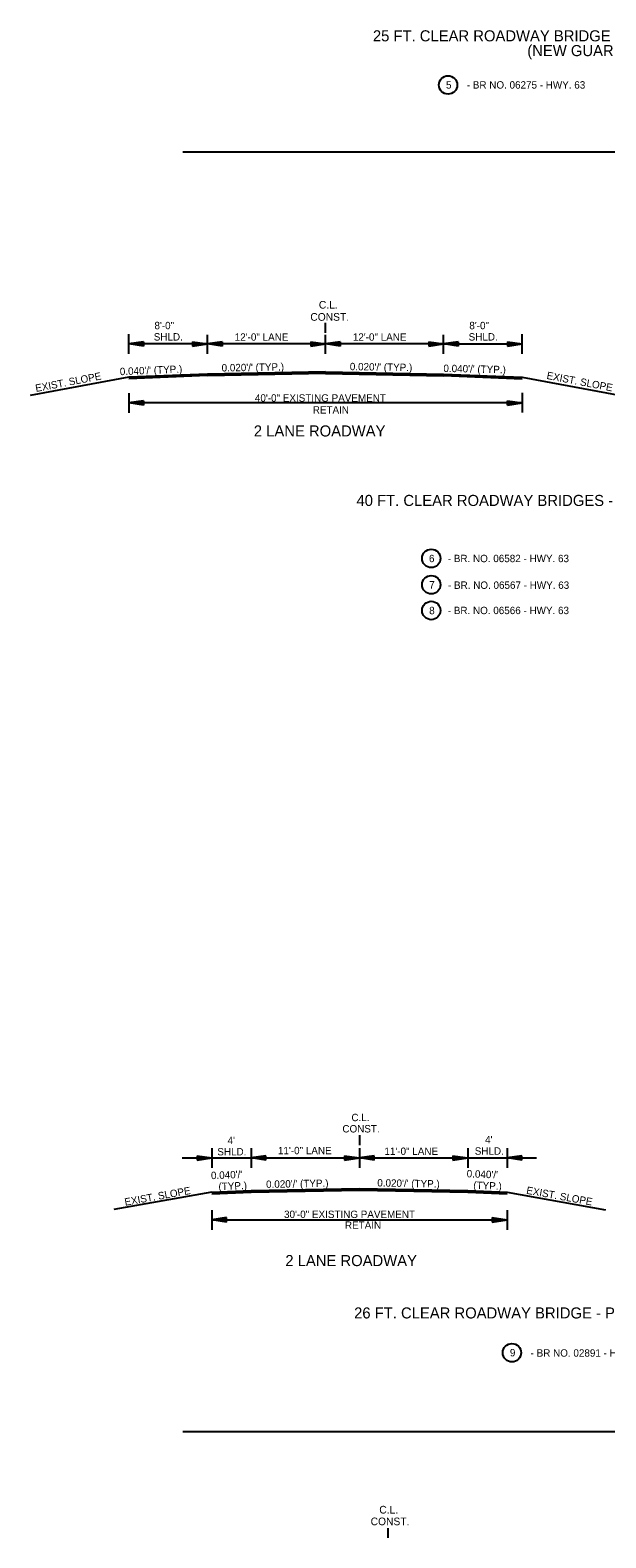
# Model space of a CAD drawing. Extents: x 545241 to 1930787, y -1971772 to 596640.
# Drawn here: x 546732 to 547317, y -1951831 to -1950299 of the extents above; entities that cross this region are included whole.
import ezdxf

# ---------------------------------------------------------------- set-up
doc = ezdxf.new("R2010")
doc.units = 0
doc.layers.add('R_Border', color=7, linetype='Continuous')
doc.layers.add('R_Draft', color=7, linetype='Continuous')

# ---------------------------------------------------------------- blocks, each defined once
blk = doc.blocks.new('ARROW')
at = {"layer": 'R_Draft'}
for p, q in [((-2, 0.3), (0, 0)), ((-2, 0.3), (-2, -0.3)), ((-2, 0.25), (-0.334, 0)), ((-2, 0.199), (-0.678, 0)), ((-2, 0.149), (-1.011, 0)), ((-2, 0.097), (-1.35, 0)), ((-2, 0.047), (-1.684, 0)), ((-2, -0.3), (0, 0)), ((-2, -0.098), (-1.35, 0)), ((-2, -0.199), (-0.678, 0)), ((-2, -0.25), (-0.334, 0)), ((-2, -0.149), (-1.011, 0)), ((-2, -0.047), (-1.684, 0))]:
    blk.add_line(p, q, dxfattribs=at)
blk = doc.blocks.new('BPPOLY')
at = {"layer": 'R_Border'}
blk.add_circle((0, 0), 9.34, dxfattribs=at)

msp = doc.modelspace()

# ---------------------------------------------------------------- linework, layer by layer
at = {"layer": 'R_Border'}
for p, q in [((546887.2, -1950422.9), (547733.9, -1950422.9)), ((547066.6, -1951422.1), (547066.6, -1951432.1)), ((546886.6, -1951445.1), (547246.6, -1951445.1)), ((546916.6, -1951435.1), (546916.6, -1951455.1)), ((546956.6, -1951435.1), (546956.6, -1951455.1)), ((547066.6, -1951435.1), (547066.6, -1951455.1)), ((547176.6, -1951435.1), (547176.6, -1951455.1)), ((547216.6, -1951435.1), (547216.6, -1951455.1)), ((546916.6, -1951479.8), (546817.1, -1951497.3)), ((547216.6, -1951479.8), (547316.6, -1951497.8)), ((546916.6, -1951498), (546916.6, -1951518)), ((546916.6, -1951508), (547216.6, -1951508)), ((547216.6, -1951498), (547216.6, -1951518)), ((546887.2, -1951722.9), (547733.9, -1951722.9))]:
    msp.add_line(p, q, dxfattribs=at)
for points in [[(546916.6, -1951479.8), (546956.6, -1951478.2), (547066.6, -1951476), (547176.6, -1951478.2), (547216.6, -1951479.8)], [(546916.6, -1951480.1), (546956.6, -1951478.5), (547066.6, -1951476.3), (547176.6, -1951478.5), (547216.6, -1951480.1)], [(546916.6, -1951480.4), (546956.6, -1951478.8), (547066.6, -1951476.6), (547176.6, -1951478.8), (547216.6, -1951480.4)], [(546916.6, -1951480.7), (546956.6, -1951479.1), (547066.6, -1951476.9), (547176.6, -1951479.1), (547216.6, -1951480.7)], [(546916.6, -1951481), (546956.6, -1951479.4), (547066.6, -1951477.2), (547176.6, -1951479.4), (547216.6, -1951481)], [(546916.6, -1951481.3), (546956.6, -1951479.7), (547066.6, -1951477.5), (547176.6, -1951479.7), (547216.6, -1951481.3)], [(546916.6, -1951481.6), (546956.6, -1951480), (547066.6, -1951477.8), (547176.6, -1951480), (547216.6, -1951481.6)]]:
    msp.add_lwpolyline(points, dxfattribs=at)
for centre in [(547156.7, -1950354.8), (547139.6, -1950835.9), (547139.6, -1950862.7), (547139.6, -1950888.8)]:
    msp.add_circle(centre, 9.34, dxfattribs=at)
at = {"layer": 'R_Draft'}
for p, q in [((547032.1, -1950606.6), (547032.1, -1950596.6)), ((546832.1, -1950627.9), (546832.1, -1950607.9)), ((546847.1, -1950615.7), (546832.1, -1950617.9)), ((546912.1, -1950617.9), (546832.1, -1950617.9)), ((546847.1, -1950620.2), (546832.1, -1950617.9)), ((546847.1, -1950616), (546834.6, -1950617.9)), ((546847.1, -1950619.8), (546834.6, -1950617.9)), ((546847.1, -1950616.4), (546837.1, -1950617.9)), ((546847.1, -1950619.4), (546837.1, -1950617.9)), ((546847.1, -1950616.8), (546839.6, -1950617.9)), ((546847.1, -1950619), (546839.6, -1950617.9)), ((546847.1, -1950617.2), (546842.2, -1950617.9)), ((546847.1, -1950618.6), (546842.2, -1950617.9)), ((546847.1, -1950617.6), (546844.7, -1950617.9)), ((546847.1, -1950618.3), (546844.7, -1950617.9)), ((546847.1, -1950615.7), (546847.1, -1950620.2)), ((546897.1, -1950615.7), (546912.1, -1950617.9)), ((546897.1, -1950615.7), (546897.1, -1950620.2)), ((546897.1, -1950616), (546909.5, -1950617.9)), ((546897.1, -1950616.4), (546907, -1950617.9)), ((546897.1, -1950616.8), (546904.5, -1950617.9)), ((546897.1, -1950617.2), (546901.9, -1950617.9)), ((546897.1, -1950617.6), (546899.4, -1950617.9)), ((546897.1, -1950620.2), (546912.1, -1950617.9)), ((546897.1, -1950618.6), (546901.9, -1950617.9)), ((546897.1, -1950619.4), (546907, -1950617.9)), ((546897.1, -1950619.8), (546909.5, -1950617.9)), ((546897.1, -1950619), (546904.5, -1950617.9)), ((546897.1, -1950618.3), (546899.4, -1950617.9)), ((546912.1, -1950627.9), (546912.1, -1950608.7)), ((546927.1, -1950615.7), (546912.1, -1950617.9)), ((547032.1, -1950617.9), (546912.1, -1950617.9)), ((546927.1, -1950620.2), (546912.1, -1950617.9)), ((546927.1, -1950616), (546914.6, -1950617.9)), ((546927.1, -1950619.8), (546914.6, -1950617.9)), ((546927.1, -1950616.4), (546917.1, -1950617.9)), ((546927.1, -1950619.4), (546917.1, -1950617.9)), ((546927.1, -1950616.8), (546919.6, -1950617.9)), ((546927.1, -1950619), (546919.6, -1950617.9)), ((546927.1, -1950617.2), (546922.2, -1950617.9)), ((546927.1, -1950618.6), (546922.2, -1950617.9)), ((546927.1, -1950617.6), (546924.7, -1950617.9)), ((546927.1, -1950618.3), (546924.7, -1950617.9)), ((546927.1, -1950615.7), (546927.1, -1950620.2)), ((547017.1, -1950615.7), (547032.1, -1950617.9)), ((547017.1, -1950615.7), (547017.1, -1950620.2)), ((547017.1, -1950616), (547029.5, -1950617.9)), ((547017.1, -1950616.4), (547027, -1950617.9)), ((547017.1, -1950616.8), (547024.5, -1950617.9)), ((547017.1, -1950617.2), (547021.9, -1950617.9)), ((547017.1, -1950617.6), (547019.4, -1950617.9)), ((547017.1, -1950620.2), (547032.1, -1950617.9)), ((547017.1, -1950618.6), (547021.9, -1950617.9)), ((547017.1, -1950619.4), (547027, -1950617.9)), ((547017.1, -1950619.8), (547029.5, -1950617.9)), ((547017.1, -1950619), (547024.5, -1950617.9)), ((547017.1, -1950618.3), (547019.4, -1950617.9)), ((547032.1, -1950627.9), (547032.1, -1950608.7)), ((547047.1, -1950615.7), (547032.1, -1950617.9)), ((547152.1, -1950617.9), (547032.1, -1950617.9)), ((547047.1, -1950620.2), (547032.1, -1950617.9)), ((547047.1, -1950616), (547034.6, -1950617.9)), ((547047.1, -1950619.8), (547034.6, -1950617.9)), ((547047.1, -1950616.4), (547037.1, -1950617.9)), ((547047.1, -1950619.4), (547037.1, -1950617.9)), ((547047.1, -1950616.8), (547039.6, -1950617.9)), ((547047.1, -1950619), (547039.6, -1950617.9)), ((547047.1, -1950617.2), (547042.2, -1950617.9)), ((547047.1, -1950618.6), (547042.2, -1950617.9)), ((547047.1, -1950617.6), (547044.7, -1950617.9)), ((547047.1, -1950618.3), (547044.7, -1950617.9)), ((547047.1, -1950615.7), (547047.1, -1950620.2)), ((547137.1, -1950615.7), (547152.1, -1950617.9)), ((547137.1, -1950615.7), (547137.1, -1950620.2)), ((547137.1, -1950616), (547149.5, -1950617.9)), ((547137.1, -1950616.4), (547147, -1950617.9)), ((547137.1, -1950616.8), (547144.5, -1950617.9)), ((547137.1, -1950617.2), (547141.9, -1950617.9)), ((547137.1, -1950617.6), (547139.4, -1950617.9)), ((547137.1, -1950620.2), (547152.1, -1950617.9)), ((547137.1, -1950618.6), (547141.9, -1950617.9)), ((547137.1, -1950619.4), (547147, -1950617.9)), ((547137.1, -1950619.8), (547149.5, -1950617.9)), ((547137.1, -1950619), (547144.5, -1950617.9)), ((547137.1, -1950618.3), (547139.4, -1950617.9)), ((547152.1, -1950627.9), (547152.1, -1950608.7)), ((547167.1, -1950615.7), (547152.1, -1950617.9)), ((547152.1, -1950617.9), (547232.1, -1950617.9)), ((547167.1, -1950620.2), (547152.1, -1950617.9)), ((547167.1, -1950616), (547154.6, -1950617.9)), ((547167.1, -1950619.8), (547154.6, -1950617.9)), ((547167.1, -1950616.4), (547157.1, -1950617.9)), ((547167.1, -1950619.4), (547157.1, -1950617.9)), ((547167.1, -1950616.8), (547159.6, -1950617.9)), ((547167.1, -1950619), (547159.6, -1950617.9)), ((547167.1, -1950617.2), (547162.2, -1950617.9)), ((547167.1, -1950618.6), (547162.2, -1950617.9)), ((547167.1, -1950617.6), (547164.7, -1950617.9)), ((547167.1, -1950618.3), (547164.7, -1950617.9)), ((547167.1, -1950615.7), (547167.1, -1950620.2)), ((547217.1, -1950615.7), (547232.1, -1950617.9)), ((547217.1, -1950615.7), (547217.1, -1950620.2)), ((547217.1, -1950616), (547229.5, -1950617.9)), ((547217.1, -1950616.4), (547227, -1950617.9)), ((547217.1, -1950616.8), (547224.5, -1950617.9)), ((547217.1, -1950617.2), (547221.9, -1950617.9)), ((547217.1, -1950617.6), (547219.4, -1950617.9)), ((547217.1, -1950620.2), (547232.1, -1950617.9)), ((547217.1, -1950618.6), (547221.9, -1950617.9)), ((547217.1, -1950619.4), (547227, -1950617.9)), ((547217.1, -1950619.8), (547229.5, -1950617.9)), ((547217.1, -1950619), (547224.5, -1950617.9)), ((547217.1, -1950618.3), (547219.4, -1950617.9)), ((547232.1, -1950627.9), (547232.1, -1950607.9)), ((546832.1, -1950651.8), (546732, -1950670.2)), ((546912.1, -1950648.6), (546832.1, -1950651.8)), ((546912.1, -1950648.9), (546832.1, -1950652.1)), ((546912.1, -1950649.2), (546832.1, -1950652.4)), ((546912.1, -1950649.5), (546832.1, -1950652.7)), ((546912.1, -1950649.8), (546832.1, -1950653)), ((546912.1, -1950650.1), (546832.1, -1950653.3)), ((547032.1, -1950646.2), (546912.1, -1950648.6)), ((547032.1, -1950646.5), (546912.1, -1950648.9)), ((547032.1, -1950646.8), (546912.1, -1950649.2)), ((547032.1, -1950647.1), (546912.1, -1950649.5)), ((547032.1, -1950647.4), (546912.1, -1950649.8)), ((547032.1, -1950647.7), (546912.1, -1950650.1)), ((547032.1, -1950647.9), (546912.1, -1950650.3)), ((547032.1, -1950646.2), (547152.1, -1950648.6)), ((547032.1, -1950646.5), (547152.1, -1950648.9)), ((547032.1, -1950646.8), (547152.1, -1950649.2)), ((547032.1, -1950647.1), (547152.1, -1950649.5)), ((547032.1, -1950647.4), (547152.1, -1950649.8)), ((547032.1, -1950647.7), (547152.1, -1950650.1)), ((547032.1, -1950647.9), (547152.1, -1950650.3)), ((547152.1, -1950648.6), (547232.1, -1950651.8)), ((547152.1, -1950648.9), (547232.1, -1950652.1)), ((547152.1, -1950649.2), (547232.1, -1950652.4)), ((547152.1, -1950649.5), (547232.1, -1950652.7)), ((547152.1, -1950649.8), (547232.1, -1950653)), ((547152.1, -1950650.1), (547232, -1950653.3)), ((547232.1, -1950651.8), (547332.1, -1950670.2)), ((547232.1, -1950667.6), (547232.1, -1950687.6)), ((546832.1, -1950667.9), (546832.1, -1950687.9)), ((546847.1, -1950675.6), (546832.1, -1950677.9)), ((546847.1, -1950680.1), (546832.1, -1950677.9)), ((547232.1, -1950677.9), (546832.1, -1950677.9)), ((546847.1, -1950676), (546834.6, -1950677.9)), ((546847.1, -1950679.8), (546834.6, -1950677.9)), ((546847.1, -1950676.4), (546837.1, -1950677.9)), ((546847.1, -1950679.4), (546837.1, -1950677.9)), ((546847.1, -1950676.8), (546839.6, -1950677.9)), ((546847.1, -1950679), (546839.6, -1950677.9)), ((546847.1, -1950677.1), (546842.2, -1950677.9)), ((546847.1, -1950678.6), (546842.2, -1950677.9)), ((546847.1, -1950677.5), (546844.7, -1950677.9)), ((546847.1, -1950678.2), (546844.7, -1950677.9)), ((546847.1, -1950675.6), (546847.1, -1950680.1)), ((547217.1, -1950675.6), (547232.1, -1950677.9)), ((547217.1, -1950680.1), (547217.1, -1950675.6)), ((547217.1, -1950676), (547229.5, -1950677.9)), ((547217.1, -1950676.4), (547227, -1950677.9)), ((547217.1, -1950676.8), (547224.5, -1950677.9)), ((547217.1, -1950677.1), (547221.9, -1950677.9)), ((547217.1, -1950677.5), (547219.4, -1950677.9)), ((547217.1, -1950680.1), (547232.1, -1950677.9)), ((547217.1, -1950678.6), (547221.9, -1950677.9)), ((547217.1, -1950679.4), (547227, -1950677.9)), ((547217.1, -1950679.8), (547229.5, -1950677.9)), ((547217.1, -1950679), (547224.5, -1950677.9)), ((547217.1, -1950678.2), (547219.4, -1950677.9)), ((547095.6, -1951821.1), (547095.6, -1951831.1))]:
    msp.add_line(p, q, dxfattribs=at)

# ---------------------------------------------------------------- block references
at = {"layer": 'R_Border', "xscale": 7.5, "yscale": 7.5}
for p in [(546916.6, -1951445.1), (547066.6, -1951445.1), (547176.6, -1951445.1), (547216.6, -1951508)]:
    msp.add_blockref('ARROW', p, dxfattribs=at)
at = {"layer": 'R_Border', "xscale": 7.5, "yscale": 7.5, "rotation": 180}
for p in [(546956.6, -1951445.1), (547066.6, -1951445.1), (547216.6, -1951445.1), (546916.6, -1951508)]:
    msp.add_blockref('ARROW', p, dxfattribs=at)
at = {"layer": 'R_Border'}
msp.add_blockref('BPPOLY', (547221.6, -1951643), dxfattribs=at)

# ---------------------------------------------------------------- texts
for s, height, p in [('25 FT. CLEAR ROADWAY BRIDGE - POLYMER OVERLAY', 11.25, (547080.3, -1950310.5)), ('(NEW GUARDRAIL)', 11.25, (547237.2, -1950325.5)), ('5', 7.5, (547154.6, -1950358.5)), ('- BR NO. 06275 - HWY. 63', 7.5, (547175.7, -1950358.5)), ('6', 7.5, (547137.3, -1950839.7)), ('7', 7.5, (547137.5, -1950866.5)), ('8', 7.5, (547137.5, -1950892.6)), ('C.L.', 7.5, (547058.5, -1951407.7)), ('CONST.', 7.5, (547049.3, -1951419.2)), ("4' ", 7.5, (546932.6, -1951431)), ('11\'-0" LANE', 7.5, (546983.8, -1951441.3)), ("4' ", 7.5, (547194.3, -1951430.3)), ('SHLD.', 7.5, (546922.2, -1951442.5)), ('11\'-0" LANE', 7.5, (547092, -1951442)), ('SHLD.', 7.5, (547183.8, -1951441.8)), ('30\'-0" EXISTING PAVEMENT', 7.5, (546990, -1951506.1)), ('RETAIN', 7.5, (547051.9, -1951517.1)), ('2 LANE ROADWAY', 11.25, (546991.3, -1951555)), ('26 FT. CLEAR ROADWAY BRIDGE - POLYMER OVERLAY', 11.25, (547061.2, -1951608.2)), ('9', 7.5, (547219.5, -1951646.7)), ('- BR NO. 02891 - HWY. 165', 7.5, (547240.6, -1951647))]:
    msp.add_text(s, height=height, dxfattribs=at).set_placement(p)
for s, rotation, p in [("0.040'/'", 2.2916, (546915.9, -1951466.7)), ("0.040'/'", 357.7084, (547175.5, -1951464.7)), ('EXIST. SLOPE', 10.204, (546828.6, -1951493.7)), ('(TYP.)', 2.2916, (546923.5, -1951477.9)), ("0.020'/' (TYP.)", 1.1458, (546971.8, -1951475.6)), ("0.020'/' (TYP.)", 358.8542, (547084.7, -1951474)), ('(TYP.)', 357.7084, (547182.2, -1951476.4)), ('EXIST. SLOPE', 349.796, (547235.8, -1951481.4))]:
    msp.add_text(s, height=7.5, rotation=rotation, dxfattribs=at).set_placement(p)
at = {"layer": 'R_Draft'}
for s, height, p in [('C.L.', 7.8, (547025.4, -1950582.1)), ('CONST.', 7.8, (547016.7, -1950594.4)), ('8\'-0"', 7.5, (546858.3, -1950603)), ('8\'-0"', 7.5, (547178.3, -1950603)), ('SHLD.', 7.5, (546857.6, -1950614.5)), ('12\'-0" LANE', 7.5, (546939.9, -1950614.7)), ('12\'-0" LANE', 7.5, (547059.9, -1950614.7)), ('SHLD.', 7.5, (547177.6, -1950614.5)), ('40\'-0" EXISTING PAVEMENT ', 7.5, (546960.4, -1950676.6)), ('RETAIN', 7.5, (547019.2, -1950688.7)), ('2 LANE ROADWAY', 11.25, (546959.3, -1950712)), ('40 FT. CLEAR ROADWAY BRIDGES - POLYMER OVERLAY', 11.25, (547063.6, -1950782.6)), ('- BR. NO. 06582 - HWY. 63', 7.5, (547156.4, -1950839.7)), ('- BR. NO. 06567 - HWY. 63', 7.5, (547156.6, -1950866.8)), ('- BR. NO. 06566 - HWY. 63', 7.5, (547156.4, -1950892.5)), ('C.L.', 7.8, (547086.8, -1951806.4)), ('CONST.', 7.8, (547078, -1951818.3))]:
    msp.add_text(s, height=height, dxfattribs=at).set_placement(p)
for s, rotation, p in [("0.020'/' (TYP.)", 0.9719, (546926.6, -1950646)), ("0.020'/' (TYP.)", 359.0281, (547056.8, -1950644.6)), ('EXIST. SLOPE', 10.8829, (546738, -1950666.8)), ("  0.040'/' (TYP.)", 2.448, (546817.7, -1950650)), ("0.040'/' (TYP.)", 358.6816, (547151.9, -1950646.4)), ('EXIST. SLOPE', 349.1171, (547256.4, -1950653.4))]:
    msp.add_text(s, height=7.5, rotation=rotation, dxfattribs=at).set_placement(p)

doc.saveas('drawing.dxf')
